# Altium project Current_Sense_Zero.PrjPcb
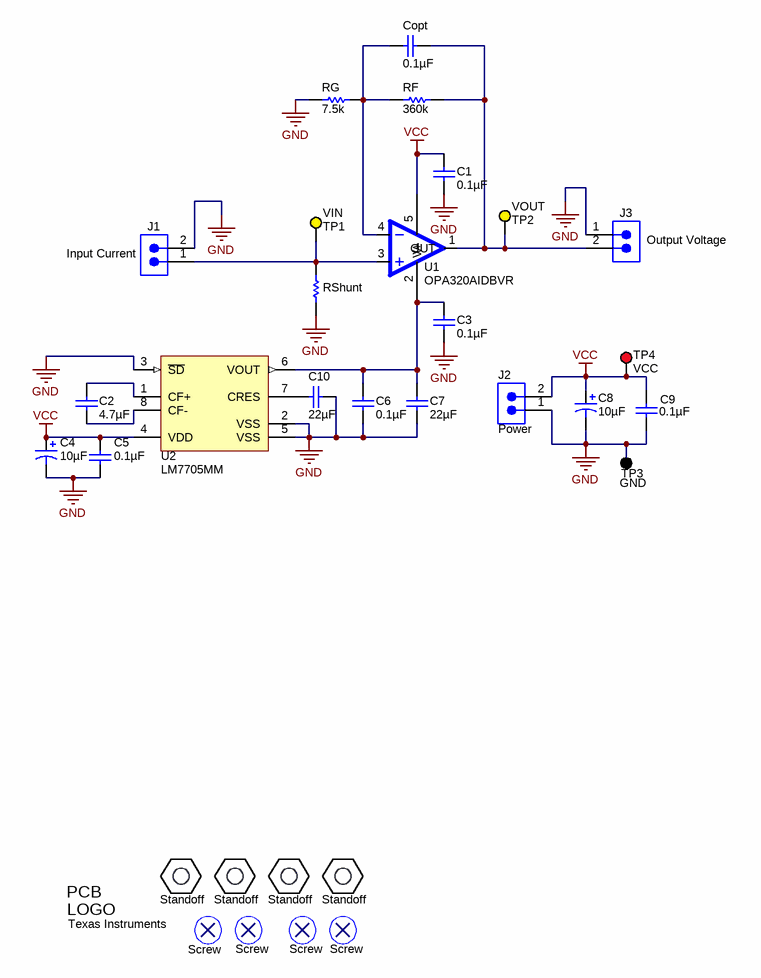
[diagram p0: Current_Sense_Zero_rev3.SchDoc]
CopyrightYear: 2013; PRJ_Customer: PA-Linear; PRJ_Title: TIPD129; SCH_Rev: 3; TechSupport: http://www.ti.com/support
1 sheet, 32 parts. Net scope: global (net labels, ports and power ports of the same name join across sheets).
Board file: Current_Sense_Zero_rev4.PcbDoc

## Sheet Current_Sense_Zero_rev3.SchDoc: Complete Schematic
size B; Date: Not shown in title block; ApprovedBy: Not shown in title block; CheckedBy: Not shown in title block; Author: Not shown in title block; CompanyName: Not shown in title block; DrawnBy: Not shown in title block; Engineer: Not shown in title block; Organization: Not shown in title block; Address1: Not shown in title block; Address2: Not shown in title block; Address3: Not shown in title block; Address4: Not shown in title block; DocumentNumber: 1; Revision: Use project parameter SCH_Rev; SheetNumber: 1; SheetTotal: 1; PageSetup: Record=PageOptions|CenterHorizontal=True|CenterVertical=True|PrintScale=0.72|XCorrection=1.00|YCorrection=1.00|PrintKind=0|BorderSize=5000000|LeftOffset=0|BottomOffset=0|Orientation=2|PaperLength=1000|PaperWidth=1000|Scale=100|PaperSource=15|PrintQuality=600|MediaType=1|DitherType=10|PaperKind=Letter|PrintScaleMode=1

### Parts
C1  ValueDisplayed: 0.1µF  [0603]  (hidden comment: 0603YC104JAT2A)
C2  ValueDisplayed: 4.7µF  [0603]  (hidden comment: C1608X5R1C475M080AC)
C3  ValueDisplayed: 0.1µF  [0603]  (hidden comment: 0603YC104JAT2A)
C4  ValueDisplayed: 10µF  [3528-21]  (hidden comment: TPSB106M020R1000)
C5  ValueDisplayed: 0.1µF  [0603]  (hidden comment: 0603YC104JAT2A)
C6  ValueDisplayed: 0.1µF  [0603]  (hidden comment: 0603YC104JAT2A)
C7  ValueDisplayed: 22µF  [0603]  (hidden comment: CL10A226MP8NUNE)
C8  ValueDisplayed: 10µF  [3528-21]  (hidden comment: TPSB106M020R1000)
C9  ValueDisplayed: 0.1µF  [0603]  (hidden comment: 0603YC104JAT2A)
C10  ValueDisplayed: 22µF  [0603]  (hidden comment: CL10A226MP8NUNE)
Copt  ValueDisplayed: 0.1µF  [0603]  (hidden comment: 0603YC104JAT2A)
J1  Input Current  [TERM_BLK_ED555-2DS]
J2  Power  [TERM_BLK_ED555-2DS]
J3  Output Voltage  [TERM_BLK_ED555-2DS]
Logo1  Texas Instruments  [TI_Symbol_Overlay_Medium]  (no BOM)
RF  value 360k  [0805_HV]  (hidden comment: RG2012N-364-W-T1)
RG  value 7.5k  [0603]  (hidden comment: RG1608N-752-W-T1)
RShunt  Y1487-.1-ND  [Multi-Pad 0805-2512]  (value not drawn)
S3  Standoff  [STANDOFF HEX 4-40THR ALUM 1"L]
S4  Standoff  [STANDOFF HEX 4-40THR ALUM 1"L]
S5  Standoff  [STANDOFF HEX 4-40THR ALUM 1"L]
S6  Standoff  [STANDOFF HEX 4-40THR ALUM 1"L]
S7  Screw  (mechanical)
S8  Screw  (mechanical)
S9  Screw  (mechanical)
S10  Screw  (mechanical)
TP1  VIN  [Keystone5009]
TP2  VOUT  [Keystone5009]
TP3  GND  [Keystone5006]
TP4  VCC  [Keystone5005]
U1  OPA320AIDBVR  [SOT23-5P]
U2  LM7705MM  [MUA08A_N]

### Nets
GND: C1.2 C3.2 C4.2(-) C5.2 C6.2 C7.2 C8.2(-) C9.2 C10.1 J1.2 J2.1 J3.1 RG.1 RShunt.1 TP3.1 U2.2(VSS) U2.3(~{SD}) U2.5(VSS)
VCC: C1.1 C4.1(+) C5.1 C8.1(+) C9.1 J2.2 TP4.1 U1.5(V+) U2.4(VDD)
NetC2_1: C2.1 U2.8(CF-)
NetC2_2: C2.2 U2.1(CF+)
NetC3_1: C3.1 C6.1 C7.1 U1.2(V-) U2.6(VOUT)
NetC10_2: C10.2 U2.7(CRES)
NetCopt_1: Copt.1 J3.2 RF.2 TP2.1 U1.1(OUT)
NetCopt_2: Copt.2 RF.1 RG.2 U1.4
NetJ1_1: J1.1 RShunt.2 TP1.1 U1.3

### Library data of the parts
C1 C3 C5 C6 C9 Copt = 0603YC104JAT2A: CAP, CERM, 0.1uF, 16V, +/-5%, X7R, 0603; Manufacturer: AVX; Polarized: N; CompType: Capacitor; U/M: EA; Cap_F: 0.0000001; Tolerance_%: 5; ESR_Ohm: 0.039; Value1: 0.039 ohm; VDC_V: 16; TaMin_C: -55; TaMax_C: 125
C2 = 0603ZD475KAT2A: CAP, CERM, 4.7uF, 10V, +/-10%, X5R, 0603; Manufacturer: TDK Corporation; Polarized: N; CompType: Capacitor; U/M: EA; Cap_F: 0.0000047; Tolerance_%: 20; Value1: Unknown; VDC_V: 16; Value2: 16V; TaMin_C: -55; TaMax_C: 85
C4 C8 = TPSB106M020R1000: CAP, TANT, 10uF, 20V, +/-20%, 1 ohm, 3528-21 SMD; Manufacturer: AVX; Polarized: Y; CompType: Capacitor; U/M: EA; Cap_F: 0.00001; Tolerance_%: 20; Value1: 1 ohm; ESR_Ohm: 1; IRMS_A: 0.262; TaMin_C: -55; TaMax_C: 125; Cap_Case: B
C7 C10 = CL10A226MP8NUNE: CAP, CERM, 22uF, 10V, +/-20%, X5R, 0603; Manufacturer: Samsung; Polarized: N; CompType: Capacitor; U/M: EA; Cap_F: 0.000022; Tolerance_%: 20; Value1: Unknown; VDC_V: 10; TaMin_C: -55; TaMax_C: 85
J1-J3 = ED555/2DS: Terminal Block, 6A, 3.5mm Pitch, 2-Pos, TH; Manufacturer: On-Shore Technology; SymbolCreator: a0412235; CompType: Connector; U/M: EA
Logo1 = TI_Logo: Texas Instrument Corporate Signature; SymbolCreator: codlsc
RF = RG2012P-364-B-T5: RES, 360k ohm, 0.1%, 0.125W, 0805; Manufacturer: Susumu Co Ltd; CompType: Resistor; Res_ohm: 360000; Tolerance_%: 0.05; Value1: 0.05%; Power_W: 0.125; VDC_V: 100; TempCo: 25 ppm/C; U/M: EA
RG = RC0603JR-077K5L: RES, 7.5k ohm, 5%, 0.1W, 0603; Manufacturer: Susumu; CompType: Resistor; Res_ohm: 7500; Value_Code: 7k50; Tolerance_%: .05; Value1: .05%; Power_W: 0.125; Value2: 0.125W; VDC_V: 50; TempCo: 100 ppm/C; EIA_Code: E24; U/M: EA
RShunt = Multi-Pad Resistor: 0805-2512 SMT Passive Pad for Shunt Resistor; Manufacturer: Vishay Foil Resistors (Division of Vishay Precision Group); SymbolCreator: a0221282; U/M: EA, IN, or GM
S3-S6 = Standoff, 1", 4-40, Alum, F-F: STANDOFF HEX 4-40THR ALUM 1"L; Manufacturer: Keystone; PartNumber: 2205; SymbolVersion: use current date i.e. 2008-05-20; SymbolCreator: Use LDAP id; CompType: Used in some BOM reports.  Useful for finding later.; U/M: EA, IN, or GM
S7-S10 = Machine Screw, 4-40, 0.25": MACHINE SCREW PAN PHILLIPS 4-40; Manufacturer: B&F Fastener Supply; PartNumber: PMSSS 440 0025 PH; SymbolVersion: use current date i.e. 2008-05-20; SymbolCreator: Use LDAP id; CompType: Mechanical; U/M: EA, IN, or GM
TP1 TP2 = 5009: Test Point, TH, Compact, Yellow; Manufacturer: Keystone; Alternate Manufacturer: Any; Alternate PartNumber: Equivalent; CompType: Test Point Loop; U/M: EA
TP3 = 5006: Test Point, TH, Compact, Black; Manufacturer: Keystone; Alternate Manufacturer: Any; Alternate PartNumber: Equivalent; CompType: Test Point Loop; U/M: EA
TP4 = 5005: Test Point, TH, Compact, Red; Manufacturer: Keystone; Alternate Manufacturer: Any; Alternate PartNumber: Equivalent; CompType: Test Point Loop; U/M: EA
U1 = OPA320AIDBVR: IC, Precision, 20MHz, 0.9pA, Low-Noise, RRIO, CMOS Op-Amp; Manufacturer: TI; Alternate Manufacturer: None; Area: 31500
U2 = LM7705MM: Low Noise Negative Bias Generator, 8-pin Mini SOIC; Manufacturer: National Semiconductor; PackageTopMarking: THHD*XTT; PowerWise: N; CompType: OtherParts

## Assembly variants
-100A: all parts fitted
